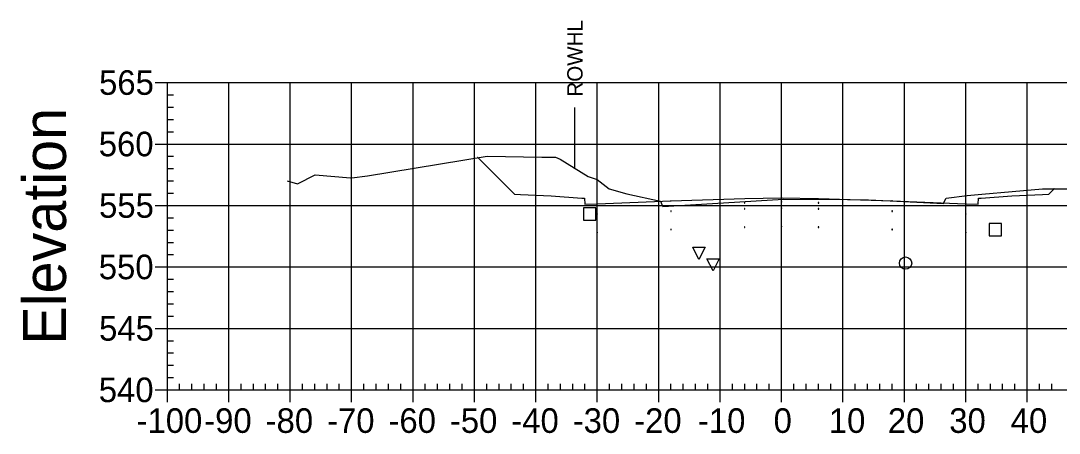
# Model space of a CAD drawing. Extents: x 708103 to 717568, y 374476 to 378707.
# Drawn here: x 710028.1 to 710197.2, y 377777.6 to 377844.7 of the extents above; entities that cross this region are included whole.
import ezdxf

# ---------------------------------------------------------------- set-up
doc = ezdxf.new("R2010")
doc.units = 0
for name, color, linetype in [('1', 7, 'Continuous'), ('10', 7, 'Continuous'), ('13', 7, 'Continuous'), ('14', 7, 'Continuous'), ('22', 7, 'Continuous'), ('4', 7, 'Continuous'), ('57', 7, 'Continuous'), ('60', 7, 'Continuous'), ('Existing', 7, 'Continuous'), ('XS_Right_of_Way', 7, 'Continuous')]:
    doc.layers.add(name, color=color, linetype=linetype)

msp = doc.modelspace()

# ---------------------------------------------------------------- linework, layer by layer
for points in [[(710145.93, 377815.03), (710146.03, 377815.03), (710146.03, 377815.13), (710145.93, 377815.13)], [(710151.93, 377815.15), (710152.03, 377815.15), (710152.03, 377815.25), (710151.93, 377815.25)], [(710157.93, 377815.03), (710158.03, 377815.03), (710158.03, 377815.13), (710157.93, 377815.13)], [(710121.93, 377813.19), (710122.03, 377813.19), (710122.03, 377813.29), (710121.93, 377813.29)], [(710133.93, 377813.67), (710134.03, 377813.67), (710134.03, 377813.77), (710133.93, 377813.77)], [(710145.93, 377814.03), (710146.03, 377814.03), (710146.03, 377814.13), (710145.93, 377814.13)], [(710151.93, 377814.15), (710152.03, 377814.15), (710152.03, 377814.25), (710151.93, 377814.25)], [(710157.93, 377814.03), (710158.03, 377814.03), (710158.03, 377814.13), (710157.93, 377814.13)], [(710169.93, 377813.67), (710170.03, 377813.67), (710170.03, 377813.77), (710169.93, 377813.77)], [(710181.93, 377813.19), (710182.03, 377813.19), (710182.03, 377813.29), (710181.93, 377813.29)], [(710121.93, 377810.19), (710122.03, 377810.19), (710122.03, 377810.29), (710121.93, 377810.29)], [(710133.93, 377810.67), (710134.03, 377810.67), (710134.03, 377810.77), (710133.93, 377810.77)], [(710145.93, 377811.03), (710146.03, 377811.03), (710146.03, 377811.13), (710145.93, 377811.13)], [(710151.93, 377811.15), (710152.03, 377811.15), (710152.03, 377811.25), (710151.93, 377811.25)], [(710157.93, 377811.03), (710158.03, 377811.03), (710158.03, 377811.13), (710157.93, 377811.13)], [(710169.93, 377810.67), (710170.03, 377810.67), (710170.03, 377810.77), (710169.93, 377810.77)], [(710181.93, 377810.19), (710182.03, 377810.19), (710182.03, 377810.29), (710181.93, 377810.29)]]:
    msp.add_lwpolyline(points, close=True)
at = {"layer": '1'}
for points in [[(710138.53, 377805.82), (710137.53, 377807.82), (710139.53, 377807.82)], [(710140.83, 377803.97), (710139.83, 377805.97), (710141.83, 377805.97)]]:
    msp.add_lwpolyline(points, close=True, dxfattribs=at)
at = {"layer": '10'}
msp.add_lwpolyline([(710119.76, 377812.25), (710121.76, 377812.25), (710121.76, 377814.25), (710119.76, 377814.25)], close=True, dxfattribs=at)
at = {"layer": '13'}
msp.add_circle((710172.18, 377805.26), 1, dxfattribs=at)
at = {"layer": '14'}
for points in [[(710102.54, 377822.41), (710102.54, 377822.46), (710102.54, 377822.41), (710102.49, 377822.41), (710102.54, 377822.41), (710102.54, 377822.36), (710102.54, 377822.41), (710102.59, 377822.41)], [(710196.35, 377817.33), (710196.35, 377817.38), (710196.35, 377817.33), (710196.3, 377817.33), (710196.35, 377817.33), (710196.35, 377817.28), (710196.35, 377817.33), (710196.4, 377817.33)], [(710121.98, 377814.9), (710121.98, 377814.95), (710121.98, 377814.9), (710121.93, 377814.9), (710121.98, 377814.9), (710121.98, 377814.85), (710121.98, 377814.9), (710122.03, 377814.9)], [(710133.98, 377815.38), (710133.98, 377815.43), (710133.98, 377815.38), (710133.93, 377815.38), (710133.98, 377815.38), (710133.98, 377815.33), (710133.98, 377815.38), (710134.03, 377815.38)], [(710151.98, 377815.86), (710151.98, 377815.91), (710151.98, 377815.86), (710151.93, 377815.86), (710151.98, 377815.86), (710151.98, 377815.81), (710151.98, 377815.86), (710152.03, 377815.86)], [(710169.98, 377815.38), (710169.98, 377815.43), (710169.98, 377815.38), (710169.93, 377815.38), (710169.98, 377815.38), (710169.98, 377815.33), (710169.98, 377815.38), (710170.03, 377815.38)], [(710181.98, 377814.9), (710181.98, 377814.95), (710181.98, 377814.9), (710181.93, 377814.9), (710181.98, 377814.9), (710181.98, 377814.85), (710181.98, 377814.9), (710182.03, 377814.9)]]:
    msp.add_lwpolyline(points, dxfattribs=at)
at = {"layer": '22'}
msp.add_lwpolyline([(710102.54, 377822.41), (710108.48, 377816.46), (710109.48, 377816.42), (710114.48, 377816.22), (710119.48, 377815.82), (710119.9, 377815.82), (710119.98, 377814.82), (710121.98, 377814.9), (710133.98, 377815.38), (710145.98, 377815.74), (710151.98, 377815.86), (710157.98, 377815.74), (710169.98, 377815.38), (710181.98, 377814.9), (710183.98, 377814.82), (710184.07, 377815.82), (710184.48, 377815.82), (710189.48, 377816.22), (710194.48, 377816.42), (710195.48, 377816.46), (710196.35, 377817.33)], dxfattribs=at)
at = {"layer": '4'}
msp.add_lwpolyline([(710185.77, 377809.67), (710187.77, 377809.67), (710187.77, 377811.67), (710185.77, 377811.67)], close=True, dxfattribs=at)
at = {"layer": '57'}
for p, q in [((710049.98, 377834.63), (710051.98, 377834.63)), ((710051.98, 377834.63), (710251.98, 377834.63)), ((710051.98, 377784.63), (710051.98, 377834.63)), ((710051.98, 377784.63), (710051.98, 377834.63)), ((710061.98, 377784.63), (710061.98, 377834.63)), ((710071.98, 377784.63), (710071.98, 377834.63)), ((710081.98, 377784.63), (710081.98, 377834.63)), ((710091.98, 377784.63), (710091.98, 377834.63)), ((710101.98, 377784.63), (710101.98, 377834.63)), ((710111.98, 377784.63), (710111.98, 377834.63)), ((710121.98, 377784.63), (710121.98, 377834.63)), ((710131.98, 377784.63), (710131.98, 377834.63)), ((710141.98, 377784.63), (710141.98, 377834.63)), ((710151.98, 377784.63), (710151.98, 377834.63)), ((710161.98, 377784.63), (710161.98, 377834.63)), ((710171.98, 377784.63), (710171.98, 377834.63)), ((710181.98, 377784.63), (710181.98, 377834.63)), ((710191.98, 377784.63), (710191.98, 377834.63)), ((710051.98, 377832.63), (710052.98, 377832.63)), ((710051.98, 377830.63), (710052.98, 377830.63)), ((710051.98, 377828.63), (710052.98, 377828.63)), ((710051.98, 377826.63), (710052.98, 377826.63)), ((710049.98, 377824.63), (710051.98, 377824.63)), ((710051.98, 377824.63), (710251.98, 377824.63)), ((710051.98, 377822.63), (710052.98, 377822.63)), ((710051.98, 377820.63), (710052.98, 377820.63)), ((710051.98, 377818.63), (710052.98, 377818.63)), ((710051.98, 377816.63), (710052.98, 377816.63)), ((710049.98, 377814.63), (710051.98, 377814.63)), ((710051.98, 377814.63), (710251.98, 377814.63)), ((710051.98, 377812.63), (710052.98, 377812.63)), ((710051.98, 377810.63), (710052.98, 377810.63)), ((710051.98, 377808.63), (710052.98, 377808.63)), ((710051.98, 377806.63), (710052.98, 377806.63)), ((710049.98, 377804.63), (710051.98, 377804.63)), ((710051.98, 377804.63), (710251.98, 377804.63)), ((710051.98, 377802.63), (710052.98, 377802.63)), ((710051.98, 377800.63), (710052.98, 377800.63)), ((710051.98, 377798.63), (710052.98, 377798.63)), ((710051.98, 377796.63), (710052.98, 377796.63)), ((710049.98, 377794.63), (710051.98, 377794.63)), ((710051.98, 377794.63), (710251.98, 377794.63)), ((710051.98, 377792.63), (710052.98, 377792.63)), ((710051.98, 377790.63), (710052.98, 377790.63)), ((710051.98, 377788.63), (710052.98, 377788.63)), ((710051.98, 377786.63), (710052.98, 377786.63)), ((710049.98, 377784.63), (710051.98, 377784.63)), ((710051.98, 377784.63), (710251.98, 377784.63)), ((710051.98, 377784.63), (710251.98, 377784.63)), ((710051.98, 377782.63), (710051.98, 377784.63)), ((710053.98, 377784.63), (710053.98, 377785.63)), ((710055.98, 377784.63), (710055.98, 377785.63)), ((710057.98, 377784.63), (710057.98, 377785.63)), ((710059.98, 377784.63), (710059.98, 377785.63)), ((710061.98, 377782.63), (710061.98, 377784.63)), ((710063.98, 377784.63), (710063.98, 377785.63)), ((710065.98, 377784.63), (710065.98, 377785.63)), ((710067.98, 377784.63), (710067.98, 377785.63)), ((710069.98, 377784.63), (710069.98, 377785.63)), ((710071.98, 377782.63), (710071.98, 377784.63)), ((710073.98, 377784.63), (710073.98, 377785.63)), ((710075.98, 377784.63), (710075.98, 377785.63)), ((710077.98, 377784.63), (710077.98, 377785.63)), ((710079.98, 377784.63), (710079.98, 377785.63)), ((710081.98, 377782.63), (710081.98, 377784.63)), ((710083.98, 377784.63), (710083.98, 377785.63)), ((710085.98, 377784.63), (710085.98, 377785.63)), ((710087.98, 377784.63), (710087.98, 377785.63)), ((710089.98, 377784.63), (710089.98, 377785.63)), ((710091.98, 377782.63), (710091.98, 377784.63)), ((710093.98, 377784.63), (710093.98, 377785.63)), ((710095.98, 377784.63), (710095.98, 377785.63)), ((710097.98, 377784.63), (710097.98, 377785.63)), ((710099.98, 377784.63), (710099.98, 377785.63)), ((710101.98, 377782.63), (710101.98, 377784.63)), ((710103.98, 377784.63), (710103.98, 377785.63)), ((710105.98, 377784.63), (710105.98, 377785.63)), ((710107.98, 377784.63), (710107.98, 377785.63)), ((710109.98, 377784.63), (710109.98, 377785.63)), ((710111.98, 377782.63), (710111.98, 377784.63)), ((710113.98, 377784.63), (710113.98, 377785.63)), ((710115.98, 377784.63), (710115.98, 377785.63)), ((710117.98, 377784.63), (710117.98, 377785.63)), ((710119.98, 377784.63), (710119.98, 377785.63)), ((710121.98, 377782.63), (710121.98, 377784.63)), ((710123.98, 377784.63), (710123.98, 377785.63)), ((710125.98, 377784.63), (710125.98, 377785.63)), ((710127.98, 377784.63), (710127.98, 377785.63)), ((710129.98, 377784.63), (710129.98, 377785.63)), ((710131.98, 377782.63), (710131.98, 377784.63)), ((710133.98, 377784.63), (710133.98, 377785.63)), ((710135.98, 377784.63), (710135.98, 377785.63)), ((710137.98, 377784.63), (710137.98, 377785.63)), ((710139.98, 377784.63), (710139.98, 377785.63)), ((710141.98, 377782.63), (710141.98, 377784.63)), ((710143.98, 377784.63), (710143.98, 377785.63)), ((710145.98, 377784.63), (710145.98, 377785.63)), ((710147.98, 377784.63), (710147.98, 377785.63)), ((710149.98, 377784.63), (710149.98, 377785.63)), ((710151.98, 377782.63), (710151.98, 377784.63)), ((710153.98, 377784.63), (710153.98, 377785.63)), ((710155.98, 377784.63), (710155.98, 377785.63)), ((710157.98, 377784.63), (710157.98, 377785.63)), ((710159.98, 377784.63), (710159.98, 377785.63)), ((710161.98, 377782.63), (710161.98, 377784.63)), ((710163.98, 377784.63), (710163.98, 377785.63)), ((710165.98, 377784.63), (710165.98, 377785.63)), ((710167.98, 377784.63), (710167.98, 377785.63)), ((710169.98, 377784.63), (710169.98, 377785.63)), ((710171.98, 377782.63), (710171.98, 377784.63)), ((710173.98, 377784.63), (710173.98, 377785.63)), ((710175.98, 377784.63), (710175.98, 377785.63)), ((710177.98, 377784.63), (710177.98, 377785.63)), ((710179.98, 377784.63), (710179.98, 377785.63)), ((710181.98, 377782.63), (710181.98, 377784.63)), ((710183.98, 377784.63), (710183.98, 377785.63)), ((710185.98, 377784.63), (710185.98, 377785.63)), ((710187.98, 377784.63), (710187.98, 377785.63)), ((710189.98, 377784.63), (710189.98, 377785.63)), ((710191.98, 377782.63), (710191.98, 377784.63)), ((710193.98, 377784.63), (710193.98, 377785.63)), ((710195.98, 377784.63), (710195.98, 377785.63))]:
    msp.add_line(p, q, dxfattribs=at)
at = {"layer": 'Existing'}
msp.add_lwpolyline([(710071.46, 377818.62), (710073.17, 377818.14), (710076.07, 377819.62), (710081.78, 377819.11), (710082.03, 377819.15), (710084.59, 377819.44), (710104.05, 377822.66), (710112.97, 377822.49), (710115.18, 377822.5), (710115.96, 377822.16), (710120.5, 377819.34), (710121.95, 377818.83), (710123.92, 377817.36), (710126.78, 377816.53), (710132.25, 377815.33), (710132.49, 377814.81), (710132.65, 377814.46), (710140.75, 377814.96), (710152.32, 377815.63), (710162.72, 377815.6), (710166.16, 377815.54), (710169.67, 377815.39), (710178.33, 377814.95), (710178.58, 377815.43), (710178.81, 377815.83), (710182.23, 377816.23), (710184.61, 377816.48), (710194.47, 377817.34), (710203.58, 377817.31)], dxfattribs=at)
at = {"layer": 'XS_Right_of_Way'}
msp.add_line((710118.27, 377830.58), (710118.27, 377820.58), dxfattribs=at)

# ---------------------------------------------------------------- texts
at = {"layer": '14'}
for p in [(710109.45, 377816.37), (710194.45, 377816.37), (710109.45, 377815.71), (710114.45, 377815.51), (710189.45, 377815.51), (710194.45, 377815.71)]:
    msp.add_text('+', height=0.1, dxfattribs=at).set_placement(p)
at = {"layer": '57'}
for s, p in [('565', (710040.86, 377832.63)), ('560', (710040.81, 377822.63)), ('555', (710040.86, 377812.63)), ('550', (710040.81, 377802.63)), ('545', (710040.86, 377792.63)), ('540', (710040.81, 377782.63)), ('-100', (710046.97, 377777.63)), ('-90', (710057.98, 377777.63)), ('-80', (710067.98, 377777.63)), ('-70', (710077.98, 377777.63)), ('-60', (710087.98, 377777.63)), ('-50', (710097.98, 377777.63)), ('-40', (710107.98, 377777.63)), ('-30', (710117.98, 377777.63)), ('-20', (710127.98, 377777.63)), ('-10', (710138.37, 377777.63)), ('0', (710150.69, 377777.63)), ('10', (710159.68, 377777.63)), ('20', (710169.29, 377777.63)), ('30', (710179.29, 377777.63)), ('40', (710189.29, 377777.63))]:
    msp.add_text(s, height=4, dxfattribs=at).set_placement(p)
at = {"layer": '60'}
msp.add_text('Elevation', height=7, rotation=90, dxfattribs=at).set_placement((710035.48, 377791.99))
at = {"layer": 'XS_Right_of_Way'}
msp.add_text('ROWHL', height=2.5, rotation=90, dxfattribs=at).set_placement((710119.59, 377832.34))

doc.saveas('drawing.dxf')
